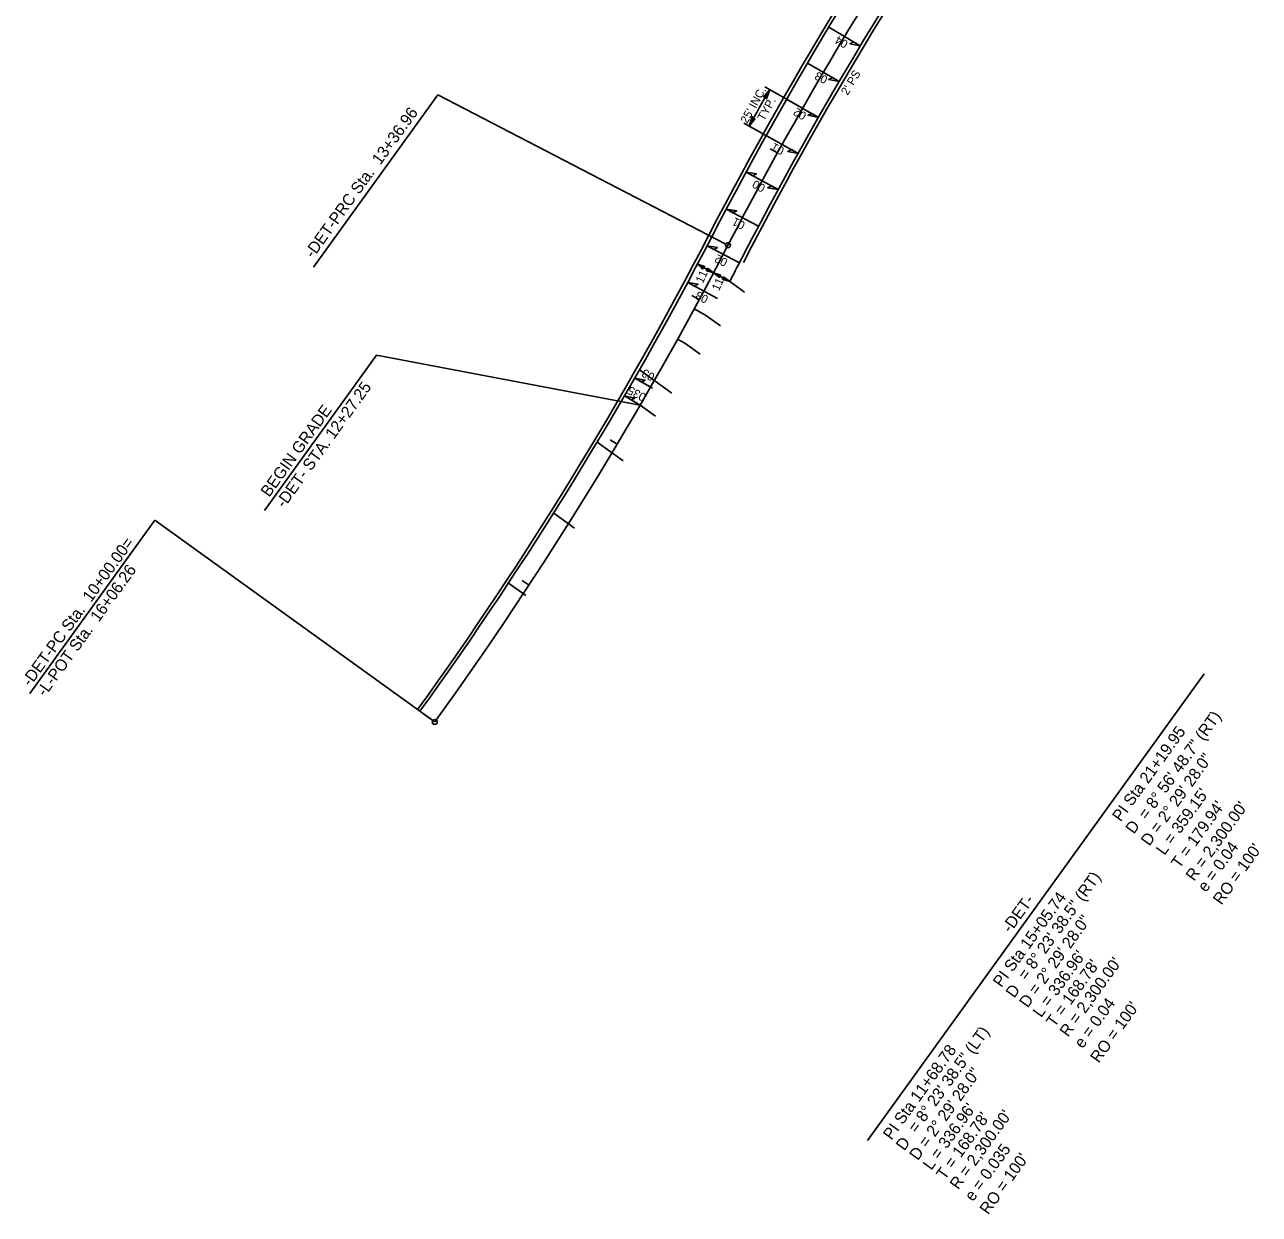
# Model space of a CAD drawing. Extents: x 2189637 to 2190858, y 386969 to 388736.
# Drawn here: x 2189637 to 2190380, y 386969 to 387684 of the extents above; entities that cross this region are included whole.
import ezdxf

# ---------------------------------------------------------------- set-up
doc = ezdxf.new("R2010")
doc.units = 0
for name, color, linetype in [('Exist Environmental Wetland Boundary', 7, 'Continuous'), ('Exist Environmental Wetland Boundary Cogo Comment', 7, 'Continuous'), ('Exist Environmental Wetland Boundary Cogo Point CELL', 7, 'Continuous'), ('Exist Horizontal Alignment Tick Label', 7, 'Continuous'), ('Exist Hydro Stream or Body of Water Leader', 7, 'Continuous'), ('Exist Hydro Swamp or Marsh', 7, 'Continuous'), ('Exist Property Corner CELL', 7, 'Continuous'), ('Exist Property Corner Cogo Elevation', 7, 'Continuous'), ('Exist Property Iron Pin CELL', 7, 'Continuous'), ('Exist Property Iron Pin Cogo Elevation', 7, 'Continuous'), ('Exist Roads EOP', 7, 'Continuous'), ('Exist Roads EOT', 7, 'Continuous'), ('Exist Roads Soil', 7, 'Continuous'), ('Prop Parcel Number Text', 7, 'Continuous'), ('Raster_Level_0', 7, 'Continuous')]:
    doc.layers.add(name, color=color, linetype=linetype)

msp = doc.modelspace()

# ---------------------------------------------------------------- linework, layer by layer
at = {"layer": 'Exist Environmental Wetland Boundary'}
msp.add_line((2190144.32, 387013.09), (2190346.82, 387293.87), dxfattribs=at)
at = {"layer": 'Exist Environmental Wetland Boundary Cogo Comment'}
for p, q in [((2190051.71, 387534.98), (2190061.44, 387529.83)), ((2190070.43, 387523.35), (2190061.44, 387529.83)), ((2190040.07, 387513.24), (2190046.78, 387509.59)), ((2190055.81, 387503.08), (2190046.78, 387509.59)), ((2190030.11, 387495.08), (2190034.51, 387492.64)), ((2190043.57, 387486.11), (2190034.51, 387492.64)), ((2190026.56, 387462.53), (2190007.11, 387476.56)), ((2190016.7, 387448.85), (2190007.6, 387455.41)), ((2189997.32, 387421.97), (2189981.76, 387433.19)), ((2189968.07, 387381.42), (2189955.53, 387390.46)), ((2189938.82, 387340.86), (2189928.4, 387348.38))]:
    msp.add_line(p, q, dxfattribs=at)
at = {"layer": 'Exist Environmental Wetland Boundary Cogo Point CELL'}
for centre, start, end in [((2192102.3, 386492.96), 144.20184, 152.59586), ((2188018.5, 388610.18), 324.20184, 332.59586)]:
    msp.add_arc(centre, 2300, start, end, dxfattribs=at)
at = {"layer": 'Exist Horizontal Alignment Tick Label'}
for p, q in [((2190090.18, 387607.13), (2190085.81, 387609.56)), ((2190043.13, 387518.9), (2190038.73, 387521.27)), ((2189993.78, 387431.93), (2189989.49, 387434.49)), ((2189940.7, 387347.19), (2189936.53, 387349.94))]:
    msp.add_line(p, q, dxfattribs=at)
at = {"layer": 'Exist Hydro Stream or Body of Water Leader'}
msp.add_line((2189883.99, 387264.84), (2189877.5, 387269.52), dxfattribs=at)
at = {"layer": 'Exist Hydro Swamp or Marsh'}
for centre, radius, start, end in [((2192102.3, 386492.96), 2311, 144.20184, 152.59586), ((2192102.3, 386492.96), 2289, 144.20184, 152.59586), ((2188018.5, 388610.18), 2289, 324.20184, 332.59586), ((2188018.5, 388610.18), 2311, 332.12917, 332.59586)]:
    msp.add_arc(centre, radius, start, end, dxfattribs=at)
at = {"layer": 'Exist Property Corner CELL'}
for centre, radius, start, end in [((2192102.3, 386492.96), 2313, 144.20184, 152.59586), ((2192102.3, 386492.96), 2287, 144.20184, 152.71824), ((2188017.43, 388608.44), 2287.15, 324.25297, 332.64699)]:
    msp.add_arc(centre, radius, start, end, dxfattribs=at)
at = {"layer": 'Exist Property Corner Cogo Elevation'}
for p, q in [((2189811.12, 387538.39), (2189885.88, 387642.05)), ((2190059.07, 387552.26), (2189885.88, 387642.05)), ((2189640.42, 387281.97), (2189715.63, 387386.26)), ((2189882.78, 387265.71), (2189715.63, 387386.26))]:
    msp.add_line(p, q, dxfattribs=at)
for centre in [(2190060.4, 387551.57), (2189883.99, 387264.84)]:
    msp.add_circle(centre, 1.5, dxfattribs=at)
at = {"layer": 'Exist Property Iron Pin Cogo Elevation'}
for p, q in [((2190121.09, 387682.72), (2190139.95, 387671.4)), ((2190108.28, 387661.12), (2190127.26, 387650)), ((2190095.7, 387639.37), (2190114.8, 387628.46)), ((2190083.35, 387617.5), (2190102.57, 387606.79)), ((2190071.25, 387595.49), (2190090.58, 387584.99)), ((2190059.39, 387573.34), (2190078.83, 387563.06)), ((2190047.78, 387551.14), (2190067.28, 387540.96)), ((2190036.15, 387529.14), (2190054.01, 387519.57)), ((2190004.33, 387471.7), (2190014.97, 387465.6)), ((2189998.11, 387460.92), (2190007.6, 387455.41))]:
    msp.add_line(p, q, dxfattribs=at)
for points in [[(2190139.95, 387671.4), (2190133.78, 387672.77), (2190135.99, 387673.78)], [(2190127.26, 387650), (2190121.07, 387651.3), (2190123.27, 387652.34)], [(2190114.8, 387628.46), (2190108.6, 387629.7), (2190110.78, 387630.76)], [(2190102.57, 387606.79), (2190096.36, 387607.96), (2190098.53, 387609.04)], [(2190071.27, 387595.53), (2190077.5, 387594.42), (2190075.34, 387593.32)], [(2190090.58, 387584.99), (2190084.36, 387586.09), (2190086.52, 387587.2)], [(2190059.39, 387573.34), (2190065.63, 387572.31), (2190063.48, 387571.18)], [(2190047.78, 387551.14), (2190054.02, 387550.1), (2190051.87, 387548.98)], [(2190036.15, 387529.14), (2190042.38, 387528.07), (2190040.22, 387526.96)], [(2190004.33, 387471.7), (2190010.53, 387470.45), (2190008.34, 387469.4)], [(2189998.11, 387460.92), (2190004.31, 387459.64), (2190002.12, 387458.6)]]:
    msp.add_lwpolyline(points, close=True, dxfattribs=at)
at = {"layer": 'Exist Roads EOP'}
for p, q in [((2190082.63, 387646.84), (2190105.25, 387633.92)), ((2190092.96, 387612.14), (2190069.99, 387624.94)), ((2190041.99, 387540.11), (2190061.44, 387529.83))]:
    msp.add_line(p, q, dxfattribs=at)
msp.add_arc((2192102.3, 386492.96), 2322.75, 150.25988, 150.88266, dxfattribs=at)
at = {"layer": 'Exist Roads Soil'}
for points in [[(2190081.76, 387640.59), (2190085.5, 387645.2), (2190083.53, 387639.56), (2190082.98, 387640.72)], [(2190076.77, 387627.87), (2190073.09, 387623.21), (2190074.99, 387628.88), (2190075.55, 387627.72)], [(2190045.63, 387537.35), (2190041.99, 387540.11), (2190046.37, 387538.73), (2190045.49, 387538.29)], [(2190048.07, 387537.73), (2190051.71, 387534.97), (2190047.33, 387536.35), (2190048.2, 387536.79)], [(2190055.35, 387532.21), (2190051.71, 387534.97), (2190056.09, 387533.6), (2190055.22, 387533.15)], [(2190057.8, 387532.59), (2190061.44, 387529.83), (2190057.05, 387531.21), (2190057.93, 387531.65)]]:
    msp.add_lwpolyline(points, close=True, dxfattribs=at)
at = {"layer": 'Raster_Level_0'}
for p, q in [((2189781.59, 387392.02), (2189848.99, 387485.48)), ((2189848.99, 387485.48), (2190007.6, 387455.41))]:
    msp.add_line(p, q, dxfattribs=at)

# ---------------------------------------------------------------- texts
at = {"layer": 'Exist Environmental Wetland Boundary'}
for s, p in [('= 8%%d 56\' 48.7" (RT)', (2190312.29, 387205.59)), ('PI Sta 21+19.95', (2190296.67, 387204.42)), ('D = 2%%d 29\' 28.0"', (2190313.92, 387189.82)), ("L = 359.15'", (2190322.99, 387184.26)), ("T = 179.94'", (2190332.12, 387176.23)), ("R = 2,300.00'", (2190340.86, 387168.69)), ('D', (2190304.62, 387197.03)), ('e = 0.04', (2190348, 387162.02)), ("RO = 100'", (2190357.27, 387154.37)), ('= 8%%d 23\' 38.5" (RT)', (2190239.87, 387108.97)), ('PI Sta 15+05.74', (2190224.88, 387104.77)), ('-DET-', (2190230.32, 387137.56)), ('D = 2%%d 29\' 28.0"', (2190240.71, 387092.52)), ("L = 336.96'", (2190248.82, 387086.67)), ("T = 168.78'", (2190256.93, 387080.82)), ("R = 2,300.00'", (2190265.04, 387074.97)), ('D', (2190232.6, 387098.37)), ('e = 0.04', (2190273.79, 387068.05)), ("RO = 100'", (2190283.46, 387059.31)), ('= 8%%d 23\' 38.5" (LT)', (2190173.78, 387017.17)), ('PI Sta 11+68.78', (2190158.78, 387012.97)), ('D = 2%%d 29\' 28.0"', (2190174.61, 387000.72)), ("L = 336.96'", (2190182.72, 386994.87)), ("T = 168.78'", (2190190.83, 386989.02)), ("R = 2,300.00'", (2190198.94, 386983.17)), ('D', (2190166.5, 387006.57)), ('e = 0.035', (2190207.84, 386976.05)), ("RO = 100'", (2190216.91, 386968.15))]:
    msp.add_text(s, height=7, rotation=54.20184, dxfattribs=at).set_placement(p)
at = {"layer": 'Exist Property Corner Cogo Elevation'}
for s, p in [('-DET-PRC Sta.  13+36.96', (2189810.79, 387543.3)), ('-DET-PC Sta.  10+00.00=', (2189640.69, 387285.81)), ('-L-POT Sta.  16+06.26', (2189649.58, 387279.74))]:
    msp.add_text(s, height=7, rotation=54.20184, dxfattribs=at).set_placement(p)
at = {"layer": 'Exist Property Iron Pin CELL'}
for s, p in [('-DET- STA. 12+27.25', (2189793.44, 387393.06)), ('BEGIN GRADE', (2189784.36, 387399.61))]:
    msp.add_text(s, height=7, rotation=54.20184, dxfattribs=at).set_placement(p)
at = {"layer": 'Exist Roads EOT'}
for s, rotation, p in [("2' PS", 59.22402, (2190132.36, 387641.39)), ("25' INC.", 60.57127, (2190071.85, 387624.25)), ('TYP.', 60.57127, (2190082.12, 387625.91)), ("11'", 65.4414, (2190045.24, 387528.24)), ("11'", 65.4414, (2190054.93, 387523.69))]:
    msp.add_text(s, height=5, rotation=rotation, dxfattribs=at).set_placement(p)
at = {"layer": 'Prop Parcel Number Text'}
for s, rotation, p in [('04', 150.0103, (2190133.12, 387673.99)), ('03', 152.1695, (2190120.87, 387652.7)), ('02', 149.67377, (2190108.06, 387630.78)), ('01', 152.86649, (2190094.72, 387609.89)), ('00', 329.87866, (2190074.4, 387586.72)), ('01', 152.86649, (2190071.2, 387565.1)), ('02', 152.34472, (2190060.64, 387542.84)), ('03', 152.1695, (2190049.1, 387520.65)), ('03', 152.1695, (2190016.83, 387473.9)), ('035', 152.1695, (2190011.59, 387461.8))]:
    msp.add_text(s, height=5, rotation=rotation, dxfattribs=at).set_placement(p)

doc.saveas('drawing.dxf')
